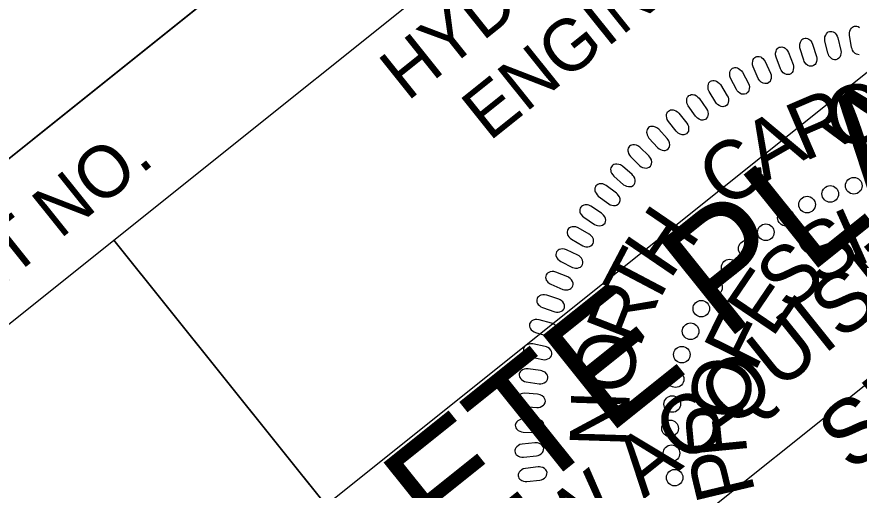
# Model space of a CAD drawing. Extents: x 473546 to 475544, y 505920 to 507827.
# Drawn here: x 474796.9 to 474878.2, y 507682.7 to 507728.4 of the extents above; entities that cross this region are included whole.
import ezdxf

# ---------------------------------------------------------------- set-up
doc = ezdxf.new("R2010")
doc.units = 0
for name, color, linetype in [('Sheet Plan CELL', 7, 'Continuous'), ('Sheet Profile Grid Minor CELL', 7, 'Continuous'), ('Sheet Sticker Incomplete CELL', 7, 'Continuous')]:
    doc.layers.add(name, color=color, linetype=linetype)

msp = doc.modelspace()

# ---------------------------------------------------------------- linework, layer by layer
at = {"layer": 'Sheet Plan CELL'}
for p, q in [((474720.354, 507654.034), (474876.517, 507779.047)), ((474720.354, 507654.034), (474876.517, 507779.047)), ((474806.271, 507706.801), (474876.553, 507619.004))]:
    msp.add_line(p, q, dxfattribs=at)
for points in [[(474704.678, 507673.621), (474860.894, 507798.628), (474876.517, 507779.047), (474720.354, 507654.034)], [(474806.271, 507706.801), (474884.328, 507769.288), (474954.641, 507681.452), (474876.574, 507618.957)], [(474728.157, 507644.284), (474806.271, 507706.801), (474876.574, 507618.957), (474798.455, 507556.468)]]:
    msp.add_lwpolyline(points, close=True, dxfattribs=at)
at = {"layer": 'Sheet Profile Grid Minor CELL'}
for points in [[(474875.188, 507724.868), (474874.903, 507726.061), (474874.888, 507726.283), (474874.906, 507726.431), (474874.976, 507726.622), (474875.044, 507726.751), (474875.135, 507726.855), (474875.228, 507726.918), (474875.332, 507726.963), (474875.446, 507726.97), (474875.569, 507726.969), (474875.685, 507726.935), (474875.81, 507726.862), (474875.887, 507726.799), (474875.987, 507726.668), (474876.087, 507726.508), (474876.146, 507726.358), (474876.445, 507725.138), (474876.463, 507724.968), (474876.452, 507724.821), (474876.402, 507724.645), (474876.325, 507724.483), (474876.249, 507724.383), (474876.11, 507724.288), (474875.969, 507724.234), (474875.815, 507724.238), (474875.702, 507724.262), (474875.555, 507724.33), (474875.399, 507724.467), (474875.292, 507724.626), (474875.233, 507724.745)], [(474872.854, 507724.197), (474872.495, 507725.369), (474872.466, 507725.59), (474872.475, 507725.739), (474872.533, 507725.934), (474872.593, 507726.067), (474872.677, 507726.177), (474872.765, 507726.245), (474872.867, 507726.298), (474872.979, 507726.311), (474873.103, 507726.317), (474873.22, 507726.291), (474873.35, 507726.226), (474873.431, 507726.168), (474873.539, 507726.045), (474873.649, 507725.89), (474873.717, 507725.744), (474874.093, 507724.545), (474874.12, 507724.376), (474874.119, 507724.23), (474874.079, 507724.051), (474874.014, 507723.884), (474873.944, 507723.78), (474873.811, 507723.677), (474873.674, 507723.614), (474873.52, 507723.608), (474873.405, 507723.625), (474873.254, 507723.683), (474873.09, 507723.81), (474872.973, 507723.962), (474872.907, 507724.077)], [(474870.612, 507723.344), (474870.18, 507724.492), (474870.137, 507724.71), (474870.137, 507724.859), (474870.182, 507725.058), (474870.235, 507725.194), (474870.311, 507725.309), (474870.395, 507725.383), (474870.493, 507725.441), (474870.605, 507725.462), (474870.728, 507725.476), (474870.847, 507725.457), (474870.979, 507725.4), (474871.064, 507725.347), (474871.179, 507725.231), (474871.299, 507725.084), (474871.376, 507724.942), (474871.826, 507723.769), (474871.865, 507723.603), (474871.872, 507723.456), (474871.845, 507723.275), (474871.788, 507723.105), (474871.726, 507722.996), (474871.6, 507722.884), (474871.467, 507722.813), (474871.313, 507722.798), (474871.198, 507722.808), (474871.044, 507722.856), (474870.872, 507722.972), (474870.746, 507723.117), (474870.672, 507723.228)], [(474868.467, 507722.423), (474867.963, 507723.542), (474867.907, 507723.757), (474867.898, 507723.906), (474867.93, 507724.107), (474867.973, 507724.246), (474868.043, 507724.365), (474868.122, 507724.444), (474868.216, 507724.509), (474868.326, 507724.537), (474868.448, 507724.559), (474868.568, 507724.547), (474868.704, 507724.499), (474868.791, 507724.451), (474868.914, 507724.342), (474869.043, 507724.203), (474869.129, 507724.067), (474869.652, 507722.924), (474869.7, 507722.76), (474869.717, 507722.615), (474869.701, 507722.433), (474869.656, 507722.259), (474869.6, 507722.146), (474869.482, 507722.027), (474869.354, 507721.948), (474869.201, 507721.923), (474869.085, 507721.925), (474868.928, 507721.964), (474868.749, 507722.069), (474868.615, 507722.206), (474868.534, 507722.311)], [(474866.371, 507721.353), (474865.798, 507722.437), (474865.729, 507722.649), (474865.71, 507722.797), (474865.73, 507722.999), (474865.764, 507723.141), (474865.826, 507723.264), (474865.9, 507723.348), (474865.99, 507723.419), (474866.098, 507723.453), (474866.218, 507723.483), (474866.339, 507723.478), (474866.478, 507723.439), (474866.568, 507723.397), (474866.697, 507723.296), (474866.834, 507723.165), (474866.929, 507723.034), (474867.522, 507721.927), (474867.581, 507721.767), (474867.607, 507721.622), (474867.602, 507721.439), (474867.568, 507721.263), (474867.52, 507721.147), (474867.409, 507721.021), (474867.286, 507720.934), (474867.135, 507720.899), (474867.02, 507720.894), (474866.861, 507720.923), (474866.676, 507721.017), (474866.532, 507721.144), (474866.445, 507721.245)], [(474864.366, 507720.115), (474863.726, 507721.161), (474863.643, 507721.368), (474863.615, 507721.514), (474863.622, 507721.717), (474863.648, 507721.862), (474863.702, 507721.988), (474863.77, 507722.077), (474863.855, 507722.152), (474863.962, 507722.194), (474864.079, 507722.231), (474864.2, 507722.234), (474864.341, 507722.204), (474864.434, 507722.167), (474864.57, 507722.075), (474864.714, 507721.952), (474864.816, 507721.828), (474865.478, 507720.76), (474865.547, 507720.603), (474865.582, 507720.462), (474865.589, 507720.278), (474865.566, 507720.101), (474865.525, 507719.982), (474865.422, 507719.849), (474865.305, 507719.754), (474865.157, 507719.71), (474865.042, 507719.698), (474864.881, 507719.716), (474864.69, 507719.799), (474864.539, 507719.917), (474864.446, 507720.012)], [(474862.412, 507718.775), (474861.707, 507719.78), (474861.612, 507719.98), (474861.575, 507720.125), (474861.569, 507720.328), (474861.585, 507720.474), (474861.631, 507720.604), (474861.695, 507720.696), (474861.775, 507720.777), (474861.878, 507720.825), (474861.993, 507720.869), (474862.113, 507720.88), (474862.256, 507720.859), (474862.351, 507720.828), (474862.492, 507720.744), (474862.644, 507720.631), (474862.754, 507720.514), (474863.481, 507719.489), (474863.561, 507719.338), (474863.604, 507719.198), (474863.622, 507719.015), (474863.611, 507718.837), (474863.577, 507718.715), (474863.483, 507718.576), (474863.372, 507718.474), (474863.227, 507718.421), (474863.112, 507718.402), (474862.951, 507718.41), (474862.756, 507718.481), (474862.598, 507718.589), (474862.498, 507718.678)], [(474860.553, 507717.322), (474859.787, 507718.28), (474859.68, 507718.474), (474859.633, 507718.617), (474859.615, 507718.819), (474859.622, 507718.965), (474859.66, 507719.098), (474859.716, 507719.194), (474859.792, 507719.28), (474859.892, 507719.334), (474860.004, 507719.386), (474860.123, 507719.404), (474860.267, 507719.392), (474860.364, 507719.366), (474860.51, 507719.292), (474860.669, 507719.189), (474860.786, 507719.078), (474861.576, 507718.102), (474861.665, 507717.955), (474861.717, 507717.818), (474861.746, 507717.638), (474861.746, 507717.458), (474861.72, 507717.336), (474861.635, 507717.191), (474861.53, 507717.082), (474861.389, 507717.02), (474861.276, 507716.993), (474861.114, 507716.991), (474860.915, 507717.049), (474860.75, 507717.147), (474860.646, 507717.23)], [(474859.688, 507716.618), (474858.863, 507717.526), (474858.688, 507717.663), (474858.556, 507717.731), (474858.358, 507717.782), (474858.213, 507717.798), (474858.076, 507717.781), (474857.972, 507717.74), (474857.876, 507717.679), (474857.806, 507717.589), (474857.738, 507717.487), (474857.7, 507717.372), (474857.69, 507717.228), (474857.7, 507717.129), (474857.75, 507716.973), (474857.826, 507716.799), (474857.917, 507716.667), (474858.757, 507715.731), (474858.887, 507715.621), (474859.014, 507715.548), (474859.188, 507715.49), (474859.365, 507715.462), (474859.49, 507715.468), (474859.647, 507715.529), (474859.771, 507715.615), (474859.855, 507715.746), (474859.899, 507715.853), (474859.926, 507716.012), (474859.9, 507716.218), (474859.829, 507716.396), (474859.765, 507716.512)], [(474857.911, 507714.936), (474857.031, 507715.79), (474856.848, 507715.917), (474856.711, 507715.976), (474856.511, 507716.014), (474856.365, 507716.02), (474856.23, 507715.996), (474856.128, 507715.948), (474856.035, 507715.882), (474855.972, 507715.787), (474855.91, 507715.681), (474855.88, 507715.564), (474855.878, 507715.42), (474855.894, 507715.321), (474855.955, 507715.168), (474856.042, 507715.001), (474856.141, 507714.873), (474857.037, 507713.993), (474857.174, 507713.891), (474857.306, 507713.826), (474857.483, 507713.779), (474857.661, 507713.762), (474857.786, 507713.777), (474857.938, 507713.847), (474858.057, 507713.941), (474858.132, 507714.076), (474858.169, 507714.186), (474858.186, 507714.346), (474858.148, 507714.55), (474858.066, 507714.723), (474857.994, 507714.835)], [(474856.282, 507713.161), (474855.351, 507713.958), (474855.159, 507714.072), (474855.019, 507714.124), (474854.817, 507714.149), (474854.671, 507714.146), (474854.537, 507714.113), (474854.439, 507714.059), (474854.351, 507713.987), (474854.293, 507713.889), (474854.238, 507713.779), (474854.215, 507713.66), (474854.223, 507713.515), (474854.245, 507713.418), (474854.315, 507713.27), (474854.412, 507713.108), (474854.519, 507712.987), (474855.469, 507712.165), (474855.613, 507712.071), (474855.748, 507712.014), (474855.927, 507711.979), (474856.107, 507711.974), (474856.23, 507711.996), (474856.378, 507712.076), (474856.49, 507712.177), (474856.557, 507712.316), (474856.587, 507712.428), (474856.594, 507712.589), (474856.543, 507712.79), (474856.45, 507712.958), (474856.371, 507713.065)], [(474854.777, 507711.352), (474853.797, 507712.089), (474853.599, 507712.191), (474853.456, 507712.234), (474853.253, 507712.246), (474853.107, 507712.234), (474852.976, 507712.192), (474852.881, 507712.133), (474852.798, 507712.055), (474852.746, 507711.954), (474852.699, 507711.84), (474852.683, 507711.72), (474852.7, 507711.577), (474852.728, 507711.481), (474852.807, 507711.337), (474852.914, 507711.182), (474853.028, 507711.068), (474854.028, 507710.306), (474854.177, 507710.222), (474854.316, 507710.174), (474854.497, 507710.15), (474854.676, 507710.156), (474854.798, 507710.186), (474854.941, 507710.275), (474855.047, 507710.383), (474855.105, 507710.526), (474855.128, 507710.639), (474855.124, 507710.801), (474855.06, 507710.998), (474854.957, 507711.16), (474854.872, 507711.262)], [(474853.343, 507709.409), (474852.318, 507710.083), (474852.115, 507710.173), (474851.97, 507710.206), (474851.766, 507710.206), (474851.621, 507710.185), (474851.493, 507710.135), (474851.402, 507710.069), (474851.324, 507709.987), (474851.278, 507709.882), (474851.238, 507709.766), (474851.23, 507709.646), (474851.256, 507709.503), (474851.29, 507709.409), (474851.378, 507709.271), (474851.495, 507709.122), (474851.616, 507709.015), (474852.661, 507708.319), (474852.815, 507708.244), (474852.957, 507708.205), (474853.139, 507708.192), (474853.317, 507708.209), (474853.437, 507708.246), (474853.574, 507708.345), (474853.673, 507708.459), (474853.722, 507708.605), (474853.737, 507708.721), (474853.724, 507708.881), (474853.648, 507709.074), (474853.535, 507709.229), (474853.443, 507709.326)], [(474852.135, 507707.397), (474851.07, 507708.005), (474850.861, 507708.081), (474850.714, 507708.106), (474850.511, 507708.092), (474850.367, 507708.063), (474850.243, 507708.005), (474850.156, 507707.934), (474850.083, 507707.846), (474850.045, 507707.738), (474850.011, 507707.62), (474850.011, 507707.499), (474850.046, 507707.359), (474850.086, 507707.268), (474850.182, 507707.135), (474850.309, 507706.994), (474850.435, 507706.895), (474851.523, 507706.266), (474851.681, 507706.201), (474851.825, 507706.171), (474852.008, 507706.169), (474852.185, 507706.197), (474852.302, 507706.242), (474852.432, 507706.349), (474852.524, 507706.469), (474852.563, 507706.618), (474852.572, 507706.734), (474852.548, 507706.894), (474852.461, 507707.082), (474852.338, 507707.229), (474852.24, 507707.319)], [(474851.065, 507705.345), (474849.964, 507705.886), (474849.751, 507705.949), (474849.602, 507705.963), (474849.4, 507705.938), (474849.259, 507705.898), (474849.138, 507705.833), (474849.056, 507705.757), (474848.989, 507705.665), (474848.957, 507705.555), (474848.931, 507705.435), (474848.939, 507705.315), (474848.982, 507705.177), (474849.028, 507705.088), (474849.132, 507704.962), (474849.267, 507704.829), (474849.4, 507704.738), (474850.525, 507704.178), (474850.687, 507704.123), (474850.832, 507704.102), (474851.015, 507704.113), (474851.19, 507704.152), (474851.304, 507704.204), (474851.427, 507704.318), (474851.511, 507704.444), (474851.541, 507704.595), (474851.542, 507704.711), (474851.509, 507704.869), (474851.41, 507705.051), (474851.278, 507705.191), (474851.175, 507705.275)], [(474850.072, 507703.252), (474848.939, 507703.722), (474848.722, 507703.772), (474848.573, 507703.777), (474848.373, 507703.739), (474848.235, 507703.691), (474848.118, 507703.618), (474848.042, 507703.537), (474847.98, 507703.441), (474847.955, 507703.33), (474847.937, 507703.208), (474847.952, 507703.088), (474848.004, 507702.953), (474848.055, 507702.867), (474848.167, 507702.748), (474848.31, 507702.623), (474848.449, 507702.542), (474849.607, 507702.053), (474849.771, 507702.009), (474849.918, 507701.997), (474850.099, 507702.018), (474850.272, 507702.068), (474850.382, 507702.127), (474850.498, 507702.25), (474850.573, 507702.38), (474850.594, 507702.533), (474850.588, 507702.649), (474850.545, 507702.805), (474850.434, 507702.98), (474850.294, 507703.111), (474850.186, 507703.188)], [(474849.211, 507701.1), (474848.05, 507701.498), (474847.83, 507701.534), (474847.682, 507701.53), (474847.485, 507701.48), (474847.35, 507701.423), (474847.238, 507701.343), (474847.166, 507701.257), (474847.111, 507701.157), (474847.093, 507701.044), (474847.083, 507700.922), (474847.105, 507700.803), (474847.165, 507700.672), (474847.221, 507700.589), (474847.341, 507700.477), (474847.492, 507700.363), (474847.635, 507700.289), (474848.822, 507699.874), (474848.989, 507699.84), (474849.136, 507699.837), (474849.316, 507699.871), (474849.484, 507699.931), (474849.591, 507699.997), (474849.699, 507700.126), (474849.766, 507700.261), (474849.777, 507700.415), (474849.764, 507700.531), (474849.711, 507700.683), (474849.589, 507700.851), (474849.441, 507700.973), (474849.329, 507701.043)], [(474848.495, 507698.792), (474847.312, 507699.117), (474847.09, 507699.139), (474846.942, 507699.126), (474846.748, 507699.062), (474846.617, 507698.997), (474846.511, 507698.91), (474846.444, 507698.82), (474846.396, 507698.717), (474846.385, 507698.604), (474846.382, 507698.481), (474846.412, 507698.364), (474846.481, 507698.236), (474846.542, 507698.158), (474846.669, 507698.053), (474846.826, 507697.948), (474846.973, 507697.884), (474848.183, 507697.544), (474848.353, 507697.521), (474848.5, 507697.527), (474848.677, 507697.571), (474848.841, 507697.643), (474848.944, 507697.715), (474849.043, 507697.851), (474849.102, 507697.99), (474849.103, 507698.144), (474849.083, 507698.258), (474849.02, 507698.408), (474848.888, 507698.568), (474848.733, 507698.68), (474848.616, 507698.743)], [(474847.895, 507696.533), (474846.693, 507696.782), (474846.472, 507696.79), (474846.324, 507696.768), (474846.135, 507696.692), (474846.008, 507696.62), (474845.907, 507696.526), (474845.847, 507696.432), (474845.805, 507696.326), (474845.801, 507696.212), (474845.806, 507696.089), (474845.843, 507695.974), (474845.92, 507695.851), (474845.985, 507695.777), (474846.119, 507695.68), (474846.282, 507695.585), (474846.434, 507695.53), (474847.662, 507695.267), (474847.833, 507695.255), (474847.979, 507695.271), (474848.153, 507695.326), (474848.312, 507695.407), (474848.411, 507695.486), (474848.501, 507695.628), (474848.551, 507695.77), (474848.542, 507695.924), (474848.515, 507696.037), (474848.443, 507696.181), (474848.301, 507696.333), (474848.139, 507696.435), (474848.018, 507696.491)], [(474847.461, 507694.214), (474846.246, 507694.388), (474846.024, 507694.382), (474845.878, 507694.35), (474845.694, 507694.263), (474845.572, 507694.183), (474845.477, 507694.083), (474845.423, 507693.985), (474845.387, 507693.877), (474845.391, 507693.763), (474845.404, 507693.64), (474845.448, 507693.528), (474845.532, 507693.41), (474845.602, 507693.339), (474845.741, 507693.252), (474845.91, 507693.167), (474846.064, 507693.123), (474847.308, 507692.937), (474847.479, 507692.935), (474847.623, 507692.96), (474847.794, 507693.026), (474847.949, 507693.117), (474848.041, 507693.202), (474848.123, 507693.349), (474848.163, 507693.495), (474848.145, 507693.648), (474848.111, 507693.759), (474848.03, 507693.899), (474847.88, 507694.041), (474847.711, 507694.133), (474847.587, 507694.181)], [(474847.168, 507691.919), (474845.946, 507692.016), (474845.724, 507691.996), (474845.581, 507691.955), (474845.402, 507691.857), (474845.285, 507691.769), (474845.197, 507691.663), (474845.149, 507691.562), (474845.12, 507691.452), (474845.131, 507691.339), (474845.152, 507691.217), (474845.203, 507691.108), (474845.294, 507690.996), (474845.369, 507690.93), (474845.512, 507690.85), (474845.687, 507690.777), (474845.844, 507690.741), (474847.096, 507690.634), (474847.267, 507690.644), (474847.41, 507690.677), (474847.576, 507690.754), (474847.724, 507690.855), (474847.811, 507690.945), (474847.883, 507691.097), (474847.915, 507691.244), (474847.887, 507691.396), (474847.846, 507691.505), (474847.756, 507691.64), (474847.597, 507691.772), (474847.423, 507691.854), (474847.297, 507691.893)], [(474847.025, 507689.516), (474845.799, 507689.536), (474845.579, 507689.502), (474845.438, 507689.452), (474845.267, 507689.343), (474845.156, 507689.248), (474845.074, 507689.137), (474845.033, 507689.033), (474845.011, 507688.921), (474845.029, 507688.809), (474845.057, 507688.689), (474845.114, 507688.583), (474845.213, 507688.477), (474845.291, 507688.415), (474845.44, 507688.346), (474845.619, 507688.283), (474845.778, 507688.258), (474847.034, 507688.23), (474847.204, 507688.249), (474847.344, 507688.292), (474847.505, 507688.379), (474847.646, 507688.489), (474847.728, 507688.585), (474847.79, 507688.741), (474847.813, 507688.889), (474847.775, 507689.04), (474847.727, 507689.145), (474847.63, 507689.274), (474847.462, 507689.396), (474847.284, 507689.467), (474847.155, 507689.498)], [(474846.898, 507687.234), (474845.678, 507687.11), (474845.464, 507687.05), (474845.33, 507686.985), (474845.173, 507686.856), (474845.073, 507686.748), (474845.006, 507686.629), (474844.977, 507686.521), (474844.968, 507686.407), (474844.999, 507686.297), (474845.041, 507686.181), (474845.111, 507686.083), (474845.221, 507685.989), (474845.306, 507685.938), (474845.462, 507685.886), (474845.647, 507685.844), (474845.807, 507685.838), (474847.058, 507685.958), (474847.225, 507685.997), (474847.359, 507686.056), (474847.509, 507686.162), (474847.636, 507686.287), (474847.706, 507686.392), (474847.749, 507686.554), (474847.754, 507686.705), (474847.699, 507686.85), (474847.639, 507686.949), (474847.527, 507687.065), (474847.347, 507687.167), (474847.161, 507687.216), (474847.029, 507687.232)], [(474847.214, 507684.896), (474845.995, 507684.762), (474845.781, 507684.701), (474845.648, 507684.634), (474845.491, 507684.504), (474845.393, 507684.396), (474845.326, 507684.276), (474845.298, 507684.167), (474845.29, 507684.053), (474845.322, 507683.944), (474845.365, 507683.829), (474845.436, 507683.731), (474845.546, 507683.638), (474845.632, 507683.587), (474845.789, 507683.536), (474845.973, 507683.496), (474846.134, 507683.492), (474847.384, 507683.621), (474847.55, 507683.662), (474847.685, 507683.722), (474847.833, 507683.828), (474847.96, 507683.955), (474848.029, 507684.06), (474848.071, 507684.223), (474848.074, 507684.374), (474848.018, 507684.518), (474847.957, 507684.616), (474847.844, 507684.732), (474847.663, 507684.832), (474847.477, 507684.88), (474847.345, 507684.895)]]:
    msp.add_lwpolyline(points, close=True, dxfattribs=at)
msp.add_lwpolyline([(474878.221, 507724.721), (474878.067, 507724.734), (474877.955, 507724.766), (474877.813, 507724.843), (474877.666, 507724.989), (474877.569, 507725.154), (474877.517, 507725.277), (474877.481, 507725.402), (474877.27, 507726.611), (474877.27, 507726.833), (474877.297, 507726.98), (474877.379, 507727.166), (474877.456, 507727.291), (474877.553, 507727.389), (474877.649, 507727.446), (474877.756, 507727.485), (474877.87, 507727.484), (474877.993, 507727.475), (474878.106, 507727.434), (474878.227, 507727.354)], dxfattribs=at)
for centre in [(474877.688, 507712.063), (474875.419, 507711.268), (474873.18, 507710.242), (474871.14, 507708.968), (474869.2, 507707.57), (474867.353, 507705.99), (474865.705, 507704.162), (474864.188, 507702.235), (474862.969, 507700.189), (474861.935, 507698.002), (474861.089, 507695.744), (474860.486, 507693.375), (474860.163, 507690.974), (474859.958, 507688.617), (474860.089, 507686.222), (474860.395, 507683.864)]:
    msp.add_circle(centre, 0.801, dxfattribs=at)
at = {"layer": 'Sheet Sticker Incomplete CELL'}
msp.add_lwpolyline([(474784.034, 507616.957), (474769.35, 507635.305), (474884.119, 507727.158), (474898.803, 507708.81)], close=True, dxfattribs=at)

# ---------------------------------------------------------------- texts
at = {"layer": 'Sheet Plan CELL'}
for s, p in [('HYDRAULICS', (474834.6, 507720.155)), ('ENGINEER', (474842.513, 507716.29)), ('R/W SHEET NO.', (474770.598, 507682.477))]:
    msp.add_text(s, height=5.0001, rotation=38.67123, dxfattribs=at).set_placement(p)
at = {"layer": 'Sheet Profile Grid Minor CELL'}
for s, height, rotation, p in [('O', 5.669, 10.30147, (474875.579, 507715.691)), ('R', 5.669, 23.28019, (474872.863, 507714.355)), ('A', 5.669, 29.76954, (474869.082, 507712.347)), ('C', 5.669, 36.2589, (474865.38, 507709.65)), ('H', 5.669, 55.72697, (474859.917, 507702.865)), ('I', 5.669, 24.08066, (474877.671, 507704.087)), ('S', 5.669, 32.02046, (474874.309, 507702.206)), ('S', 5.669, 39.96025, (474871.358, 507699.714)), ('T', 5.669, 62.21633, (474858.316, 507699.778)), ('E', 5.669, 55.83985, (474869.797, 507697.236)), ('R', 5.669, 68.70569, (474857, 507696.268)), ('F', 5.669, 63.77965, (474868.111, 507693.916)), ('SEAL', 6.2363, 38.65259, (474877.476, 507684.253)), ('O', 5.669, 81.6844, (474856.179, 507691.732)), ('O', 5.669, 79.65924, (474867.186, 507689.156)), ('N', 5.669, 88.17375, (474855.912, 507686.709)), ('R', 5.669, 95.53884, (474867.439, 507686.097)), ('P', 5.669, 103.47864, (474868.223, 507682.418))]:
    msp.add_text(s, height=height, rotation=rotation, dxfattribs=at).set_placement(p)
at = {"layer": 'Sheet Sticker Incomplete CELL'}
for s, height, p in [('INCOMPLETE PLANS', 11.52, (474783.711, 507631.684)), ('DO NOT USE FOR R/W ACQUISITION', 5.76, (474790.591, 507628.289))]:
    msp.add_text(s, height=height, rotation=38.67122, dxfattribs=at).set_placement(p)

doc.saveas('drawing.dxf')
